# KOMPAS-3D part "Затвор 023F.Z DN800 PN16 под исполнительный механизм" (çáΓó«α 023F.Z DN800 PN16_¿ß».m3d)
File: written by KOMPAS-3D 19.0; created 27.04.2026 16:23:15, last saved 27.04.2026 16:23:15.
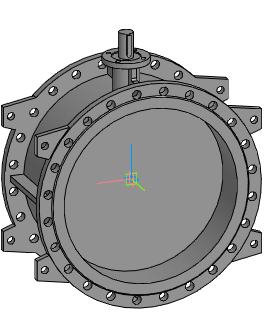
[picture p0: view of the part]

Document properties: Автор: Евгений; Полное имя файла: Z:\3.Личные\kachalov\3d для проектировщиков\1.7 Тип 023F.Z Затвор дисковый поворотный фланцевый с двумя эксцентриками\Затвор 023F.Z DN200-DN1600_исп\_stp_Затвор 023F.Z DN200-DN1600_исп\Затвор 023F.Z DN800 PN16_исп.m3d

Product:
- Part/product: Затвор 023F.Z DN800 PN16 под исполнительный механизм

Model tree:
1. Операция без истории:1  (labels: Затвор 023F.Z DN800 PN16 под исполнительный механизм)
